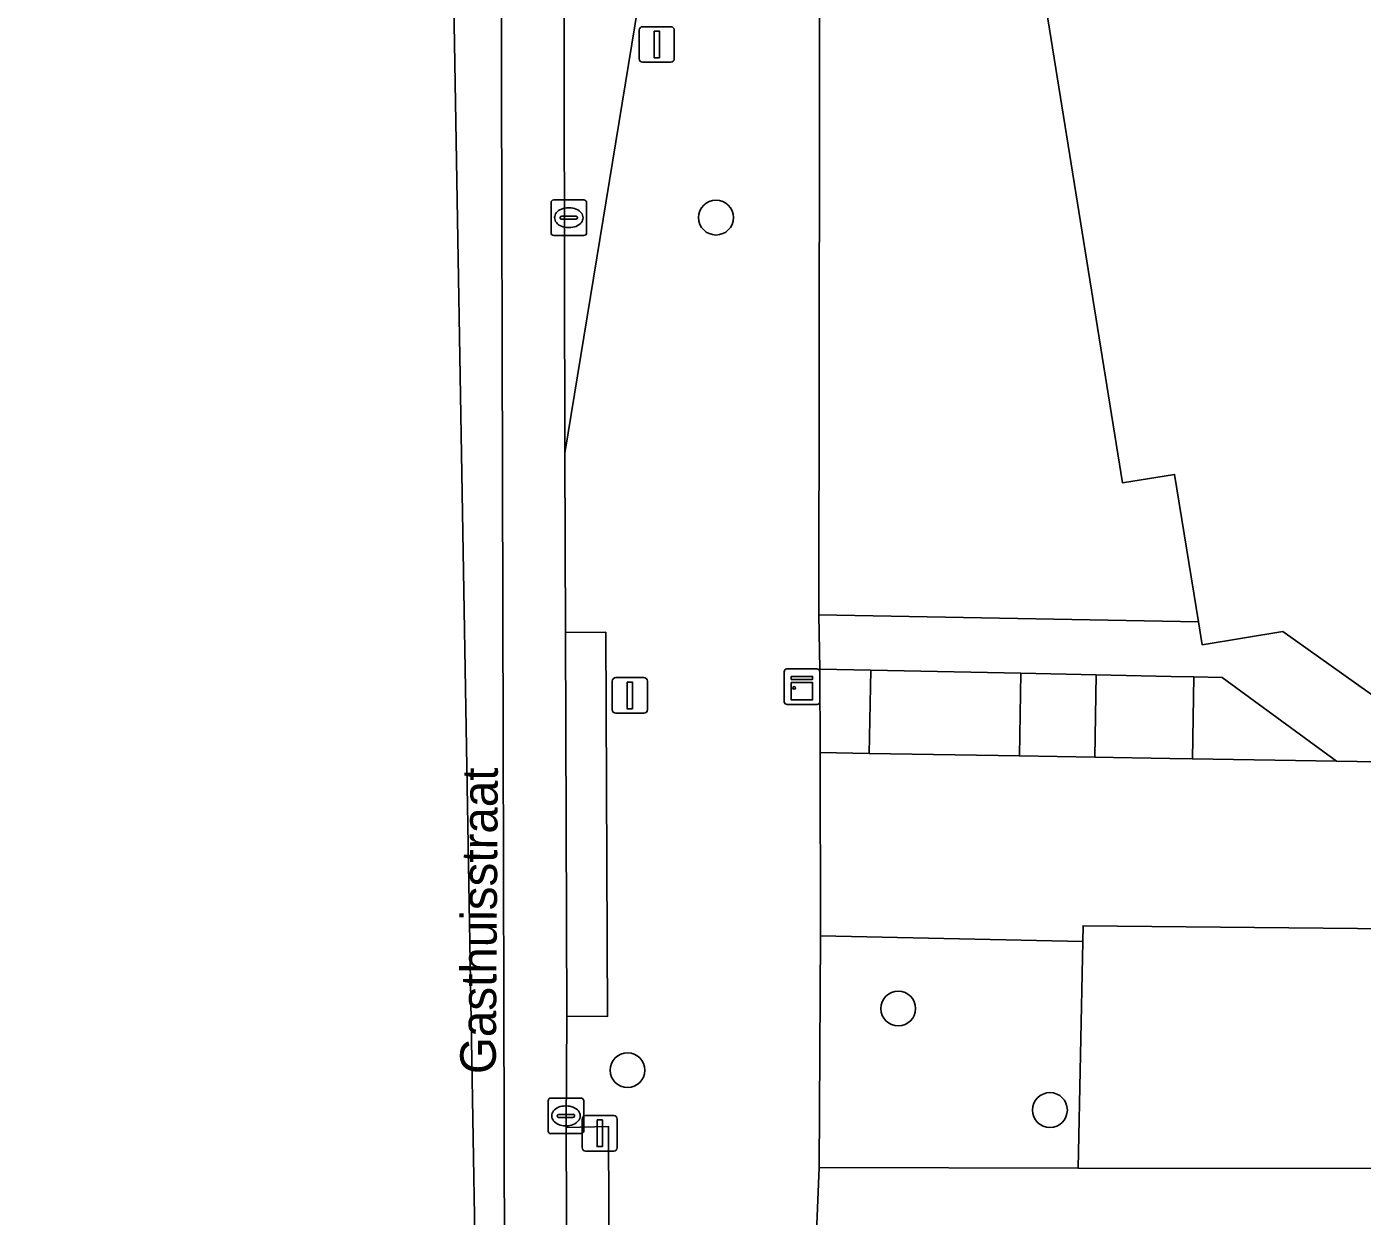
# Model space of a CAD drawing. Extents: x 162073 to 163043, y 381818 to 382561.
# Drawn here: x 162079.65 to 162117.21, y 382284.65 to 382318.1 of the extents above; entities that cross this region are included whole.
import ezdxf

# ---------------------------------------------------------------- set-up
doc = ezdxf.new("R2010")
doc.units = 0
for name, color, linetype in [('IMGEO_Boom', 7, 'Continuous'), ('IMGEO_Erf', 7, 'Continuous'), ('IMGEO_Groenvoorziening', 7, 'Continuous'), ('IMGEO_Kast', 7, 'Continuous'), ('IMGEO_Kolk', 7, 'Continuous'), ('IMGEO_Lichtmast', 7, 'Continuous'), ('IMGEO_Openbare_ruimte_label', 7, 'Continuous'), ('IMGEO_Pand', 7, 'Continuous'), ('IMGEO_Parkeervlak_open', 7, 'Continuous'), ('IMGEO_Rijbaan_lokaal_gesloten', 7, 'Continuous'), ('IMGEO_Rijbaan_lokaal_open', 7, 'Continuous'), ('IMGEO_Verkeersregelinstallatiepaal', 7, 'Continuous'), ('IMGEO_Voetpad_open', 7, 'Continuous')]:
    doc.layers.add(name, color=color, linetype=linetype)

msp = doc.modelspace()

# ---------------------------------------------------------------- linework, layer by layer
at = {"layer": 'IMGEO_Boom'}
for centre in [(162099.035, 382312.73), (162104.162, 382290.492), (162096.547, 382288.758), (162108.428, 382287.639)]:
    msp.add_circle(centre, 0.489, dxfattribs=at)
at = {"layer": 'IMGEO_Erf'}
msp.add_lwpolyline([(162106.61, 382336.736), (162105.463, 382336.559), (162104.238, 382343.879), (162101.986, 382343.468), (162101.931, 382301.562), (162112.605, 382301.364), (162111.933, 382305.51), (162110.466, 382305.274), (162107.888, 382321.303), (162109.062, 382321.492)], close=True, dxfattribs=at)
msp.add_lwpolyline([(162143.029, 382279.064), (162143.016, 382285.765), (162134.394, 382285.891), (162133.13, 382285.909), (162128.138, 382285.982), (162109.222, 382286.009), (162101.939, 382286.02), (162101.824, 382283.276)], dxfattribs=at)
at = {"layer": 'IMGEO_Groenvoorziening'}
for points in [[(162103.386, 382300.009), (162101.954, 382300.039), (162101.962, 382297.689), (162103.347, 382297.666)], [(162113.267, 382299.802), (162112.473, 382299.819), (162112.434, 382297.513), (162116.489, 382297.445)], [(162109.222, 382286.009), (162109.357, 382292.378), (162101.97, 382292.535), (162101.939, 382286.02)]]:
    msp.add_lwpolyline(points, close=True, dxfattribs=at)
at = {"layer": 'IMGEO_Kast'}
for p, q in [((162100.956, 382299.117), (162100.956, 382299.958)), ((162100.956, 382299.958), (162100.956, 382299.117)), ((162101.031, 382300.042), (162101.872, 382300.042)), ((162101.872, 382300.042), (162101.031, 382300.042)), ((162101.956, 382299.967), (162101.956, 382299.126)), ((162101.956, 382299.126), (162101.956, 382299.967)), ((162101.881, 382299.042), (162101.04, 382299.042)), ((162101.04, 382299.042), (162101.881, 382299.042))]:
    msp.add_line(p, q, dxfattribs=at)
for points in [[(162101.151, 382299.832), (162101.751, 382299.832), (162101.751, 382299.747), (162101.151, 382299.747), (162101.151, 382299.832)], [(162101.151, 382299.657), (162101.751, 382299.657), (162101.751, 382299.168), (162101.151, 382299.168), (162101.151, 382299.657)]]:
    msp.add_lwpolyline(points, dxfattribs=at)
msp.add_circle((162101.235, 382299.506), 0.0377, dxfattribs=at)
for centre, start, end in [((162101.034, 382299.964), 92.4484, 184.2845), ((162101.034, 382299.964), 92.4484, 184.2845), ((162101.878, 382299.964), 2.4484, 94.2845), ((162101.878, 382299.964), 2.4484, 94.2845), ((162101.034, 382299.12), 182.4484, 274.2845), ((162101.034, 382299.12), 182.4484, 274.2845), ((162101.878, 382299.12), 272.4484, 4.2845), ((162101.878, 382299.12), 272.4484, 4.2845)]:
    msp.add_arc(centre, 0.0779, start, end, dxfattribs=at)
at = {"layer": 'IMGEO_Kolk'}
for p, q in [((162094.395, 382312.302), (162094.395, 382313.154)), ((162094.47, 382313.228), (162095.322, 382313.228)), ((162094.883, 382313.008), (162094.908, 382313.008)), ((162095.396, 382313.154), (162095.396, 382312.302)), ((162094.654, 382312.722), (162094.654, 382312.734)), ((162095.092, 382312.685), (162094.694, 382312.685)), ((162094.697, 382312.771), (162095.095, 382312.771)), ((162095.138, 382312.734), (162095.138, 382312.722)), ((162095.322, 382312.228), (162094.47, 382312.228)), ((162094.906, 382312.448), (162094.881, 382312.448)), ((162094.314, 382287.049), (162094.314, 382287.901)), ((162094.389, 382287.975), (162095.241, 382287.975)), ((162095.315, 382287.901), (162095.315, 382287.049)), ((162094.573, 382287.469), (162094.573, 382287.481)), ((162095.011, 382287.432), (162094.613, 382287.432)), ((162094.616, 382287.518), (162095.014, 382287.518)), ((162094.802, 382287.755), (162094.827, 382287.755)), ((162095.057, 382287.481), (162095.057, 382287.469)), ((162094.825, 382287.195), (162094.8, 382287.195)), ((162095.241, 382286.975), (162094.389, 382286.975))]:
    msp.add_line(p, q, dxfattribs=at)
for points in [[(162094.395, 382312.302), (162094.395, 382313.154)], [(162094.47, 382313.228), (162095.322, 382313.228)], [(162095.396, 382313.154), (162095.396, 382312.302)], [(162095.322, 382312.228), (162094.47, 382312.228)], [(162094.314, 382287.049), (162094.314, 382287.901)], [(162094.389, 382287.975), (162095.241, 382287.975)], [(162095.315, 382287.901), (162095.315, 382287.049)], [(162095.241, 382286.975), (162094.389, 382286.975)]]:
    msp.add_lwpolyline(points, dxfattribs=at)
for centre, radius, start, end in [((162094.472, 382313.152), 0.0765, 91.552, 178.448), ((162094.472, 382313.152), 0.0765, 91.552, 178.448), ((162095.32, 382313.152), 0.0765, 1.552, 88.448), ((162095.32, 382313.152), 0.0765, 1.552, 88.448), ((162094.694, 382312.731), 0.0403, 85.8775, 175.7526), ((162094.691, 382312.721), 0.0366, 178.938, 274.7102), ((162095.095, 382312.728), 0.043, 264.8664, 352.4533), ((162095.099, 382312.733), 0.0386, 1.7309, 96.639), ((162094.472, 382312.304), 0.0765, 181.552, 268.448), ((162094.472, 382312.304), 0.0765, 181.552, 268.448), ((162095.32, 382312.304), 0.0765, 271.552, 358.448), ((162095.32, 382312.304), 0.0765, 271.552, 358.448), ((162094.391, 382287.899), 0.0765, 91.552, 178.448), ((162094.391, 382287.899), 0.0765, 91.552, 178.448), ((162095.239, 382287.899), 0.0765, 1.552, 88.448), ((162095.239, 382287.899), 0.0765, 1.552, 88.448), ((162094.613, 382287.478), 0.0403, 85.8775, 175.7526), ((162094.61, 382287.468), 0.0366, 178.938, 274.7102), ((162095.014, 382287.475), 0.043, 264.8664, 352.4533), ((162095.018, 382287.48), 0.0386, 1.7309, 96.639), ((162094.391, 382287.051), 0.0765, 181.552, 268.448), ((162094.391, 382287.051), 0.0765, 181.552, 268.448), ((162095.239, 382287.051), 0.0765, 271.552, 358.448), ((162095.239, 382287.051), 0.0765, 271.552, 358.448)]:
    msp.add_arc(centre, radius, start, end, dxfattribs=at)
for centre, major_axis, ratio, start_param, end_param in [((162094.882, 382312.728), (-0.387, 0.002), 0.722429, 4.712389, 7.853982), ((162094.907, 382312.728), (-0.39, 0.002), 0.717154, 1.570796, 4.712389), ((162094.801, 382287.475), (-0.387, 0.002), 0.722429, 4.712389, 7.853982), ((162094.826, 382287.475), (-0.39, 0.002), 0.717154, 1.570796, 4.712389)]:
    msp.add_ellipse(centre, major_axis=major_axis, ratio=ratio, start_param=start_param, end_param=end_param, dxfattribs=at)
at = {"layer": 'IMGEO_Lichtmast'}
for p, q in [((162096.873, 382317.198), (162096.873, 382317.998)), ((162096.873, 382317.998), (162096.873, 382317.198)), ((162096.973, 382318.098), (162097.763, 382318.098)), ((162097.763, 382318.098), (162096.973, 382318.098)), ((162097.863, 382317.998), (162097.863, 382317.198)), ((162097.863, 382317.198), (162097.863, 382317.998)), ((162097.763, 382317.098), (162096.973, 382317.098)), ((162096.973, 382317.098), (162097.763, 382317.098)), ((162095.369, 382287.485), (162096.159, 382287.485)), ((162096.159, 382287.485), (162095.369, 382287.485)), ((162095.269, 382286.585), (162095.269, 382287.385)), ((162095.269, 382287.385), (162095.269, 382286.585)), ((162096.259, 382287.385), (162096.259, 382286.585)), ((162096.259, 382286.585), (162096.259, 382287.385)), ((162096.159, 382286.485), (162095.369, 382286.485)), ((162095.369, 382286.485), (162096.159, 382286.485))]:
    msp.add_line(p, q, dxfattribs=at)
for points in [[(162097.293, 382317.973), (162097.443, 382317.973), (162097.443, 382317.223), (162097.293, 382317.223), (162097.293, 382317.973)], [(162095.689, 382287.36), (162095.839, 382287.36), (162095.839, 382286.61), (162095.689, 382286.61), (162095.689, 382287.36)]]:
    msp.add_lwpolyline(points, dxfattribs=at)
for centre, start, end in [((162096.973, 382317.998), 90, 180), ((162096.973, 382317.998), 90, 180), ((162097.763, 382317.998), 0, 90), ((162097.763, 382317.998), 360, 90), ((162096.973, 382317.198), 180, 270), ((162096.973, 382317.198), 180, 270), ((162097.763, 382317.198), 270, 0), ((162097.763, 382317.198), 270, 0), ((162095.369, 382287.385), 90, 180), ((162095.369, 382287.385), 90, 180), ((162096.159, 382287.385), 0, 90), ((162096.159, 382287.385), 360, 90), ((162095.369, 382286.585), 180, 270), ((162095.369, 382286.585), 180, 270), ((162096.159, 382286.585), 270, 0), ((162096.159, 382286.585), 270, 0)]:
    msp.add_arc(centre, 0.1, start, end, dxfattribs=at)
at = {"layer": 'IMGEO_Pand'}
msp.add_lwpolyline([(162104.569, 382363.942), (162107.106, 382348.54), (162107.172, 382348.136), (162108.494, 382348.353), (162109.027, 382345.08), (162106.49, 382344.643), (162107.768, 382336.938), (162106.61, 382336.736), (162109.062, 382321.492), (162107.888, 382321.303), (162110.466, 382305.274), (162111.933, 382305.51), (162112.605, 382301.364), (162112.71, 382300.721), (162114.982, 382301.089), (162118.768, 382298.404)], dxfattribs=at)
at = {"layer": 'IMGEO_Parkeervlak_open'}
msp.add_lwpolyline([(162128.138, 382285.982), (162133.13, 382285.909), (162133.115, 382291.307), (162118.021, 382291.554), (162118.042, 382292.73), (162109.362, 382292.819), (162109.357, 382292.378), (162109.222, 382286.009)], close=True, dxfattribs=at)
at = {"layer": 'IMGEO_Rijbaan_lokaal_gesloten'}
for points in [[(162092.899, 382357.108), (162093.137, 382264.876), (162094.885, 382264.932), (162094.85, 382281.967), (162094.838, 382282.232), (162094.825, 382287.149), (162094.839, 382290.276), (162094.801, 382301.067), (162094.781, 382306.112), (162094.687, 382358.914), (162094.476, 382360.162)], [(162094.687, 382358.914), (162094.781, 382306.112), (162097.478, 382322.54), (162097.542, 382323.439), (162097.495, 382342.3), (162097.477, 382347.346), (162097.499, 382352.197)]]:
    msp.add_lwpolyline(points, dxfattribs=at)
at = {"layer": 'IMGEO_Rijbaan_lokaal_open'}
msp.add_lwpolyline([(162079.649, 382368.872), (162091.125, 382350.041), (162092.112, 382292.35), (162092.582, 382264.872), (162093.137, 382264.876), (162092.899, 382357.108)], dxfattribs=at)
msp.add_lwpolyline([(162136.278, 382296.847), (162136.316, 382297.097), (162136.094, 382297.122), (162134.244, 382297.154), (162124.487, 382297.321), (162123.491, 382297.338), (162116.489, 382297.445), (162112.434, 382297.513), (162111.799, 382297.524), (162109.694, 382297.559), (162107.571, 382297.595), (162103.347, 382297.666), (162101.962, 382297.689), (162101.97, 382292.535), (162109.357, 382292.378), (162109.362, 382292.819), (162118.042, 382292.73), (162118.021, 382291.554), (162133.115, 382291.307), (162134.435, 382291.373), (162135.605, 382291.649), (162135.633, 382291.844)], close=True, dxfattribs=at)
at = {"layer": 'IMGEO_Verkeersregelinstallatiepaal'}
for p, q in [((162096.217, 382299.796), (162097.007, 382299.796)), ((162097.007, 382299.796), (162096.217, 382299.796)), ((162096.117, 382298.896), (162096.117, 382299.696)), ((162096.117, 382299.696), (162096.117, 382298.896)), ((162097.107, 382299.696), (162097.107, 382298.896)), ((162097.107, 382298.896), (162097.107, 382299.696)), ((162097.007, 382298.796), (162096.217, 382298.796)), ((162096.217, 382298.796), (162097.007, 382298.796))]:
    msp.add_line(p, q, dxfattribs=at)
msp.add_lwpolyline([(162096.537, 382299.671), (162096.687, 382299.671), (162096.687, 382298.921), (162096.537, 382298.921), (162096.537, 382299.671)], dxfattribs=at)
for centre, start, end in [((162096.217, 382299.696), 90, 180), ((162096.217, 382299.696), 90, 180), ((162097.007, 382299.696), 0, 90), ((162097.007, 382299.696), 360, 90), ((162096.217, 382298.896), 180, 270), ((162096.217, 382298.896), 180, 270), ((162097.007, 382298.896), 270, 0), ((162097.007, 382298.896), 270, 0)]:
    msp.add_arc(centre, 0.1, start, end, dxfattribs=at)
at = {"layer": 'IMGEO_Voetpad_open'}
for points in [[(162097.499, 382352.197), (162097.477, 382347.346), (162098.623, 382347.326), (162098.619, 382342.261), (162097.495, 382342.3), (162097.542, 382323.439), (162097.478, 382322.54), (162094.781, 382306.112), (162094.801, 382301.067), (162095.937, 382301.072), (162095.984, 382290.271), (162094.839, 382290.276), (162094.825, 382287.149), (162096.01, 382287.177), (162096.028, 382282.223), (162094.838, 382282.232), (162094.85, 382281.967)], [(162099.121, 382197.87), (162101.855, 382200.535), (162101.832, 382201.309), (162101.99, 382201.313), (162101.912, 382204.071), (162101.788, 382205.303), (162101.597, 382212.694), (162101.406, 382220.07), (162101.221, 382227.228), (162101.03, 382234.622), (162100.891, 382240.002), (162100.737, 382245.969), (162100.633, 382250), (162100.463, 382256.572), (162100.29, 382263.285), (162100.136, 382269.243), (162099.774, 382283.238), (162101.824, 382283.276), (162101.939, 382286.02), (162101.97, 382292.535), (162101.962, 382297.689), (162101.954, 382300.039), (162101.931, 382301.562), (162101.986, 382343.468)]]:
    msp.add_lwpolyline(points, dxfattribs=at)
for points in [[(162114.982, 382301.089), (162112.71, 382300.721), (162112.605, 382301.364), (162101.931, 382301.562), (162101.954, 382300.039), (162103.386, 382300.009), (162107.611, 382299.92), (162109.732, 382299.876), (162111.838, 382299.832), (162112.473, 382299.819), (162113.267, 382299.802), (162116.489, 382297.445), (162123.491, 382297.338), (162124.487, 382297.321), (162124.236, 382299.14), (162126.184, 382299.562), (162125.875, 382301.67), (162120.479, 382300.799), (162118.768, 382298.404)], [(162094.839, 382290.276), (162095.984, 382290.271), (162095.937, 382301.072), (162094.801, 382301.067)], [(162107.611, 382299.92), (162103.386, 382300.009), (162103.347, 382297.666), (162107.571, 382297.595)], [(162109.732, 382299.876), (162107.611, 382299.92), (162107.571, 382297.595), (162109.694, 382297.559)], [(162112.473, 382299.819), (162111.838, 382299.832), (162109.732, 382299.876), (162109.694, 382297.559), (162111.799, 382297.524), (162112.434, 382297.513)], [(162094.825, 382287.149), (162094.838, 382282.232), (162096.028, 382282.223), (162096.01, 382287.177)]]:
    msp.add_lwpolyline(points, close=True, dxfattribs=at)

# ---------------------------------------------------------------- texts
at = {"layer": 'IMGEO_Openbare_ruimte_label'}
msp.add_text('Gasthuisstraat', height=1, rotation=89.5989, dxfattribs=at).set_placement((162092.84, 382288.646))

doc.saveas('drawing.dxf')
